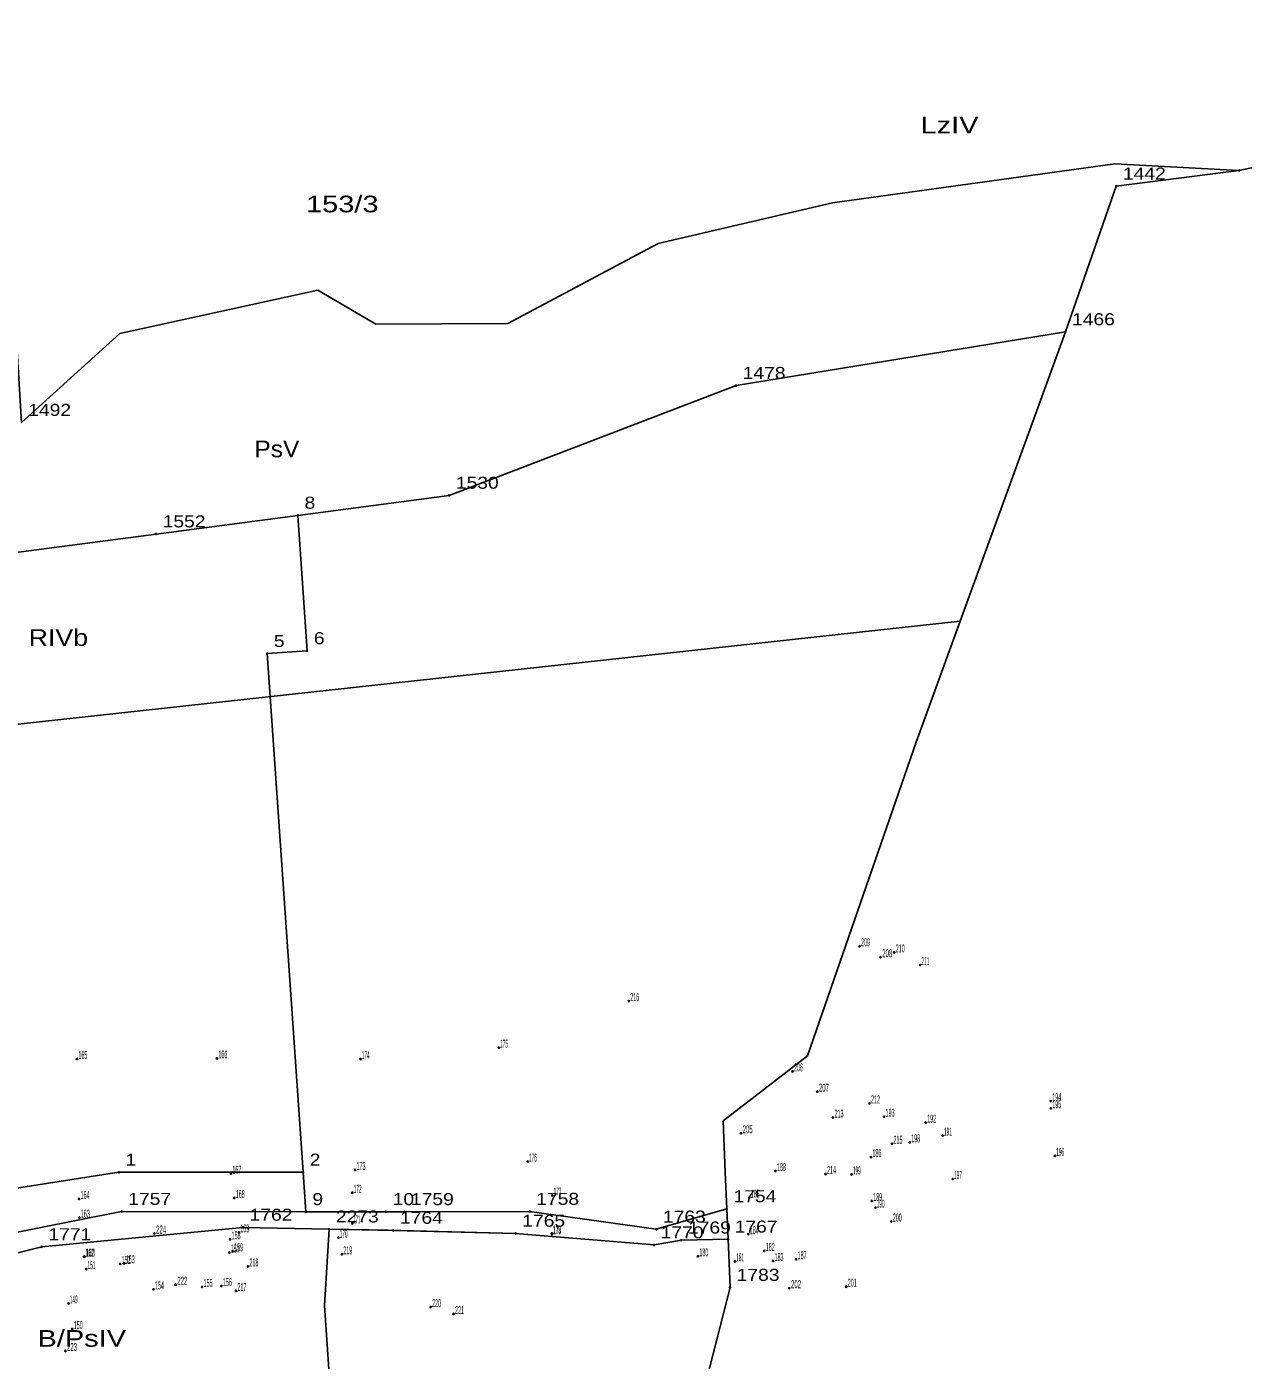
# Model space of a CAD drawing. Extents: x 4640203 to 4641683, y 5358965 to 5360242.
# Drawn here: x 4641163.8 to 4641255, y 5359988.8 to 5360088.9 of the extents above; entities that cross this region are included whole.
import ezdxf

# ---------------------------------------------------------------- set-up
doc = ezdxf.new("R2010")
doc.units = 0
doc.header["$LTSCALE"] = 0.36
doc.layers.add('24', color=7, linetype='Continuous')
doc.layers.add('26', color=7, linetype='Continuous')
for name, color, linetype, lineweight in [('25', 7, 'Continuous', 25), ('27', 7, 'Continuous', 25), ('63', 7, 'Continuous', 25), ('8', 7, 'Continuous', 25)]:
    doc.layers.add(name, color=color, linetype=linetype, lineweight=lineweight)

msp = doc.modelspace()

# ---------------------------------------------------------------- linework, layer by layer
at = {"layer": '25'}
msp.add_line((4641184.73, 5359999.98), (4641184.53, 5360002.94), dxfattribs=at)
for points in [[(4641151.72, 5360047.94), (4641173.5, 5360050.81), (4641184.14, 5360052.21), (4641195.49, 5360053.71), (4641217, 5360061.94), (4641241.7, 5360065.97), (4641245.52, 5360076.9), (4641254.72, 5360078.07), (4641265.56, 5360080.37)], [(4641139.68, 5359998.09), (4641170.72, 5360002.94), (4641184.53, 5360002.94), (4641181.84, 5360041.84), (4641184.84, 5360042.05), (4641184.14, 5360052.21)], [(4641158.71, 5359995.79), (4641164.93, 5359997.35), (4641180.02, 5359998.81), (4641186.49, 5359998.68), (4641191.3, 5359998.58), (4641200.47, 5359998.36), (4641210.85, 5359997.49), (4641212.9, 5359997.85), (4641216.4, 5359997.92), (4641216.31, 5360000.2), (4641211.02, 5359998.67), (4641201.52, 5360000), (4641192.12, 5359999.98), (4641190.75, 5359999.98), (4641184.73, 5359999.98), (4641170.92, 5360000), (4641145.57, 5359994.97)], [(4641124.54, 5359992.92), (4641124.61, 5359989.61), (4641124.88, 5359976.54), (4641158.96, 5359977.43), (4641186.91, 5359979.03), (4641212.95, 5359980.26), (4641216.55, 5359994.3), (4641216.4, 5359997.92)]]:
    msp.add_lwpolyline(points, dxfattribs=at)
at = {"layer": '27'}
for points in [[(4641256.47, 5360097.81), (4641247.03, 5360099.15), (4641232.91, 5360100.84), (4641215.68, 5360091.36), (4641196.97, 5360092.27), (4641179.55, 5360092.08), (4641161.24, 5360094.8), (4641163.42, 5360059.17), (4641170.79, 5360065.86), (4641185.64, 5360069.11), (4641189.99, 5360066.54), (4641199.88, 5360066.6), (4641211.17, 5360072.59), (4641224.24, 5360075.65), (4641233.66, 5360076.96), (4641245.4, 5360078.58), (4641254.72, 5360078.07), (4641265.56, 5360080.37)], [(4641241.7, 5360065.97), (4641245.52, 5360076.9), (4641254.72, 5360078.07)], [(4641233.82, 5360044.27), (4641241.7, 5360065.97), (4641217, 5360061.94), (4641195.49, 5360053.71), (4641184.14, 5360052.21), (4641173.5, 5360050.81), (4641151.72, 5360047.94), (4641132.16, 5360045.29), (4641115.06, 5360042.61), (4641102.5, 5360040.4), (4641098.15, 5360039.71), (4641089.62, 5360038.35), (4641066.2, 5360034.85), (4641054.92, 5360034.23), (4641049.01, 5360031.54), (4641040.7, 5360028.74), (4641036.69, 5360026.02)], [(4641216.31, 5360000.2), (4641216.18, 5360002.94), (4641216.03, 5360006.8), (4641222.35, 5360011.68), (4641230.52, 5360035.19), (4641233.82, 5360044.27), (4641141.19, 5360034.16), (4641052.15, 5360025.2), (4641039.9, 5359991.64)], [(4641186.49, 5359998.68), (4641190.9, 5359998.59), (4641200.47, 5359998.36), (4641210.85, 5359997.49), (4641212.9, 5359997.85), (4641216.4, 5359997.92), (4641216.31, 5360000.2), (4641211.02, 5359998.67), (4641201.52, 5360000), (4641192.12, 5359999.98), (4641190.75, 5359999.98), (4641184.73, 5359999.98), (4641170.92, 5360000), (4641145.57, 5359994.97), (4641140.14, 5359994.9), (4641120.73, 5359995.15), (4641111.55, 5359994.83), (4641066.92, 5359989.11), (4641045.09, 5359990.59), (4641039.9, 5359991.64), (4641023.69, 5359994.9)]]:
    msp.add_lwpolyline(points, dxfattribs=at)
msp.add_lwpolyline([(4641158.71, 5359995.79), (4641158.96, 5359977.43), (4641186.91, 5359979.03), (4641186.81, 5359983.04), (4641186.13, 5359992.94), (4641186.49, 5359998.68), (4641180.02, 5359998.81), (4641164.93, 5359997.35)], close=True, dxfattribs=at)
at = {"layer": '63'}
for centre in [(4641226.27, 5360019.89), (4641226.27, 5360019.89), (4641228.87, 5360019.43), (4641228.87, 5360019.43), (4641227.84, 5360019.07), (4641227.84, 5360019.07), (4641230.81, 5360018.48), (4641230.81, 5360018.48), (4641208.96, 5360015.78), (4641208.96, 5360015.78), (4641167.57, 5360011.44), (4641167.57, 5360011.44), (4641178.07, 5360011.48), (4641178.07, 5360011.48), (4641188.84, 5360011.43), (4641188.84, 5360011.43), (4641199.21, 5360012.29), (4641199.21, 5360012.29), (4641221.24, 5360010.51), (4641221.24, 5360010.51), (4641223.09, 5360008.99), (4641223.09, 5360008.99), (4641227.01, 5360008.11), (4641227.01, 5360008.11), (4641240.61, 5360008.28), (4641240.61, 5360008.28), (4641240.61, 5360007.74), (4641240.61, 5360007.74), (4641224.28, 5360007.05), (4641224.28, 5360007.05), (4641228.11, 5360007.11), (4641228.11, 5360007.11), (4641231.23, 5360006.67), (4641231.23, 5360006.67), (4641217.37, 5360005.87), (4641217.37, 5360005.87), (4641232.5, 5360005.69), (4641232.5, 5360005.69), (4641228.7, 5360005.08), (4641228.7, 5360005.08), (4641230.03, 5360005.19), (4641230.03, 5360005.19), (4641201.38, 5360003.75), (4641201.38, 5360003.75), (4641227.12, 5360004.08), (4641227.12, 5360004.08), (4641240.92, 5360004.17), (4641240.92, 5360004.17), (4641179.12, 5360002.84), (4641179.12, 5360002.84), (4641188.43, 5360003.12), (4641188.43, 5360003.12), (4641219.96, 5360003.03), (4641219.96, 5360003.03), (4641223.72, 5360002.81), (4641223.72, 5360002.81), (4641225.67, 5360002.78), (4641225.67, 5360002.78), (4641233.26, 5360002.44), (4641233.26, 5360002.44), (4641188.23, 5360001.41), (4641188.23, 5360001.41), (4641167.73, 5360000.94), (4641167.73, 5360000.94), (4641179.37, 5360001.02), (4641179.37, 5360001.02), (4641203.22, 5360001.2), (4641203.22, 5360001.2), (4641217.99, 5360001.04), (4641217.99, 5360001.04), (4641227.18, 5360000.79), (4641227.18, 5360000.79), (4641167.75, 5359999.54), (4641167.75, 5359999.54), (4641227.46, 5360000.29), (4641227.46, 5360000.29), (4641179.71, 5359998.44), (4641179.71, 5359998.44), (4641188.23, 5359999.11), (4641188.23, 5359999.11), (4641228.65, 5359999.25), (4641228.65, 5359999.25), (4641173.38, 5359998.35), (4641173.38, 5359998.35), (4641179.06, 5359997.91), (4641179.06, 5359997.91), (4641187.18, 5359998.04), (4641187.18, 5359998.04), (4641203.18, 5359998.36), (4641203.18, 5359998.36), (4641203.2, 5359998.29), (4641203.2, 5359998.29), (4641217.93, 5359998.3), (4641217.93, 5359998.3), (4641168.09, 5359996.61), (4641168.09, 5359996.61), (4641168.14, 5359996.62), (4641168.14, 5359996.62), (4641179, 5359996.92), (4641179, 5359996.92), (4641179.25, 5359997.02), (4641179.25, 5359997.02), (4641187.44, 5359996.79), (4641187.44, 5359996.79), (4641214.14, 5359996.64), (4641214.14, 5359996.64), (4641219.12, 5359997.05), (4641219.12, 5359997.05), (4641221.51, 5359996.42), (4641221.51, 5359996.42), (4641168.27, 5359995.68), (4641168.27, 5359995.68), (4641170.81, 5359996.07), (4641170.81, 5359996.07), (4641171.12, 5359996.11), (4641171.12, 5359996.11), (4641180.4, 5359995.88), (4641180.4, 5359995.88), (4641216.92, 5359996.26), (4641216.92, 5359996.26), (4641219.78, 5359996.29), (4641219.78, 5359996.29), (4641174.97, 5359994.51), (4641174.97, 5359994.51), (4641178.41, 5359994.41), (4641178.41, 5359994.41), (4641173.31, 5359994.16), (4641173.31, 5359994.16), (4641176.96, 5359994.35), (4641176.96, 5359994.35), (4641179.5, 5359994.04), (4641179.5, 5359994.04), (4641221, 5359994.25), (4641221, 5359994.25), (4641225.27, 5359994.36), (4641225.27, 5359994.36), (4641166.94, 5359993.11), (4641166.94, 5359993.11), (4641194.1, 5359992.83), (4641194.1, 5359992.83), (4641195.82, 5359992.32), (4641195.82, 5359992.32), (4641167.22, 5359991.18), (4641167.22, 5359991.18), (4641166.7, 5359989.54), (4641166.7, 5359989.54)]:
    msp.add_circle(centre, 0.05, dxfattribs=at)
at = {"layer": '8'}
for centre in [(4641254.72, 5360078.07), (4641245.52, 5360076.9), (4641241.7, 5360065.97), (4641217, 5360061.94), (4641195.49, 5360053.71), (4641184.14, 5360052.21), (4641173.5, 5360050.81), (4641181.84, 5360041.84), (4641184.84, 5360042.05), (4641170.72, 5360002.94), (4641184.53, 5360002.94), (4641170.92, 5360000), (4641184.73, 5359999.98), (4641190.75, 5359999.98), (4641192.12, 5359999.98), (4641201.52, 5360000), (4641216.31, 5360000.2), (4641180.02, 5359998.81), (4641186.49, 5359998.68), (4641191.3, 5359998.58), (4641211.02, 5359998.67), (4641200.47, 5359998.36), (4641210.85, 5359997.49), (4641212.9, 5359997.85), (4641216.4, 5359997.92), (4641164.93, 5359997.35), (4641216.55, 5359994.3)]:
    msp.add_circle(centre, 0.045, dxfattribs=at)

# ---------------------------------------------------------------- texts
at = {"layer": '24', "width": 1.3}
msp.add_text('153/3', height=1.25, dxfattribs=at).set_placement((4641184.75, 5360074.94))
at = {"layer": '26'}
for s, width, p in [('LzIV', 1.3, (4641230.84, 5360080.86)), ('PsV', 1.1, (4641180.88, 5360056.57)), ('RIVb', 1.2, (4641163.95, 5360042.42)), ('B/PsIV', 1.3, (4641164.61, 5359989.86))]:
    msp.add_text(s, height=1.25, dxfattribs=dict(at, width=width)).set_placement(p)
at = {"layer": '63'}
for s, width, p in [(' 209', 0.4, (4641226.27, 5360019.89)), (' 209', 0.4, (4641226.27, 5360019.89)), (' 208', 0.45, (4641227.84, 5360019.07)), (' 208', 0.45, (4641227.84, 5360019.07)), (' 210', 0.4, (4641228.87, 5360019.43)), (' 210', 0.4, (4641228.87, 5360019.43)), (' 211', 0.35, (4641230.81, 5360018.48)), (' 211', 0.35, (4641230.81, 5360018.48)), (' 216', 0.4, (4641208.96, 5360015.78)), (' 216', 0.4, (4641208.96, 5360015.78)), (' 175', 0.35, (4641199.21, 5360012.29)), (' 175', 0.35, (4641199.21, 5360012.29)), (' 165', 0.4, (4641167.57, 5360011.44)), (' 165', 0.4, (4641167.57, 5360011.44)), (' 166', 0.4, (4641178.07, 5360011.48)), (' 166', 0.4, (4641178.07, 5360011.48)), (' 174', 0.35, (4641188.84, 5360011.43)), (' 174', 0.35, (4641188.84, 5360011.43)), (' 206', 0.4, (4641221.24, 5360010.51)), (' 206', 0.4, (4641221.24, 5360010.51)), (' 207', 0.45, (4641223.09, 5360008.99)), (' 207', 0.45, (4641223.09, 5360008.99)), (' 212', 0.4, (4641227.01, 5360008.11)), (' 212', 0.4, (4641227.01, 5360008.11)), (' 194', 0.4, (4641240.61, 5360008.28)), (' 194', 0.4, (4641240.61, 5360008.28)), (' 213', 0.4, (4641224.28, 5360007.05)), (' 213', 0.4, (4641224.28, 5360007.05)), (' 193', 0.4, (4641228.11, 5360007.11)), (' 193', 0.4, (4641228.11, 5360007.11)), (' 195', 0.4, (4641240.61, 5360007.74)), (' 195', 0.4, (4641240.61, 5360007.74)), (' 205', 0.45, (4641217.37, 5360005.87)), (' 205', 0.45, (4641217.37, 5360005.87)), (' 192', 0.4, (4641231.23, 5360006.67)), (' 192', 0.4, (4641231.23, 5360006.67)), (' 215', 0.4, (4641228.7, 5360005.08)), (' 215', 0.4, (4641228.7, 5360005.08)), (' 198', 0.4, (4641230.03, 5360005.19)), (' 198', 0.4, (4641230.03, 5360005.19)), (' 191', 0.35, (4641232.5, 5360005.69)), (' 191', 0.35, (4641232.5, 5360005.69)), (' 186', 0.4, (4641227.12, 5360004.08)), (' 186', 0.4, (4641227.12, 5360004.08)), (' 196', 0.35, (4641240.92, 5360004.17)), (' 196', 0.35, (4641240.92, 5360004.17)), (' 167', 0.4, (4641179.12, 5360002.84)), (' 167', 0.4, (4641179.12, 5360002.84)), (' 173', 0.4, (4641188.43, 5360003.12)), (' 173', 0.4, (4641188.43, 5360003.12)), (' 176', 0.35, (4641201.38, 5360003.75)), (' 176', 0.35, (4641201.38, 5360003.75)), (' 188', 0.4, (4641219.96, 5360003.03)), (' 188', 0.4, (4641219.96, 5360003.03)), (' 214', 0.4, (4641223.72, 5360002.81)), (' 214', 0.4, (4641223.72, 5360002.81)), (' 199', 0.35, (4641225.67, 5360002.78)), (' 199', 0.35, (4641225.67, 5360002.78)), (' 197', 0.35, (4641233.26, 5360002.44)), (' 197', 0.35, (4641233.26, 5360002.44)), (' 164', 0.4, (4641167.73, 5360000.94)), (' 164', 0.4, (4641167.73, 5360000.94)), (' 168', 0.4, (4641179.37, 5360001.02)), (' 168', 0.4, (4641179.37, 5360001.02)), (' 172', 0.35, (4641188.23, 5360001.41)), (' 172', 0.35, (4641188.23, 5360001.41)), (' 177', 0.35, (4641203.22, 5360001.2)), (' 177', 0.35, (4641203.22, 5360001.2)), (' 185', 0.4, (4641217.99, 5360001.04)), (' 185', 0.4, (4641217.99, 5360001.04)), (' 189', 0.4, (4641227.18, 5360000.79)), (' 189', 0.4, (4641227.18, 5360000.79)), (' 190', 0.35, (4641227.46, 5360000.29)), (' 190', 0.35, (4641227.46, 5360000.29)), (' 163', 0.4, (4641167.75, 5359999.54)), (' 163', 0.4, (4641167.75, 5359999.54)), (' 171', 0.3, (4641188.23, 5359999.11)), (' 171', 0.3, (4641188.23, 5359999.11)), (' 200', 0.4, (4641228.65, 5359999.25)), (' 200', 0.4, (4641228.65, 5359999.25)), (' 224', 0.45, (4641173.38, 5359998.35)), (' 224', 0.45, (4641173.38, 5359998.35)), (' 158', 0.4, (4641179.06, 5359997.91)), (' 158', 0.4, (4641179.06, 5359997.91)), (' 169', 0.4, (4641179.71, 5359998.44)), (' 169', 0.4, (4641179.71, 5359998.44)), (' 170', 0.35, (4641187.18, 5359998.04)), (' 170', 0.35, (4641187.18, 5359998.04)), (' 179', 0.35, (4641203.18, 5359998.36)), (' 179', 0.35, (4641203.18, 5359998.36)), (' 178', 0.35, (4641203.2, 5359998.29)), (' 178', 0.35, (4641203.2, 5359998.29)), (' 184', 0.4, (4641217.93, 5359998.3)), (' 184', 0.4, (4641217.93, 5359998.3)), (' 157', 0.4, (4641179, 5359996.92)), (' 157', 0.4, (4641179, 5359996.92)), (' 159', 0.4, (4641179.25, 5359997.02)), (' 159', 0.4, (4641179.25, 5359997.02)), (' 182', 0.4, (4641219.12, 5359997.05)), (' 182', 0.4, (4641219.12, 5359997.05)), (' 162', 0.4, (4641168.09, 5359996.61)), (' 162', 0.4, (4641168.09, 5359996.61)), (' 160', 0.4, (4641168.14, 5359996.62)), (' 160', 0.4, (4641168.14, 5359996.62)), (' 152', 0.4, (4641170.81, 5359996.07)), (' 152', 0.4, (4641170.81, 5359996.07)), (' 153', 0.4, (4641171.12, 5359996.11)), (' 153', 0.4, (4641171.12, 5359996.11)), (' 218', 0.4, (4641180.4, 5359995.88)), (' 218', 0.4, (4641180.4, 5359995.88)), (' 219', 0.4, (4641187.44, 5359996.79)), (' 219', 0.4, (4641187.44, 5359996.79)), (' 180', 0.4, (4641214.14, 5359996.64)), (' 180', 0.4, (4641214.14, 5359996.64)), (' 181', 0.35, (4641216.92, 5359996.26)), (' 181', 0.35, (4641216.92, 5359996.26)), (' 183', 0.4, (4641219.78, 5359996.29)), (' 183', 0.4, (4641219.78, 5359996.29)), (' 187', 0.4, (4641221.51, 5359996.42)), (' 187', 0.4, (4641221.51, 5359996.42)), (' 151', 0.35, (4641168.27, 5359995.68)), (' 151', 0.35, (4641168.27, 5359995.68)), (' 154', 0.4, (4641173.31, 5359994.16)), (' 154', 0.4, (4641173.31, 5359994.16)), (' 222', 0.45, (4641174.97, 5359994.51)), (' 222', 0.45, (4641174.97, 5359994.51)), (' 155', 0.4, (4641176.96, 5359994.35)), (' 155', 0.4, (4641176.96, 5359994.35)), (' 156', 0.4, (4641178.41, 5359994.41)), (' 156', 0.4, (4641178.41, 5359994.41)), (' 217', 0.4, (4641179.5, 5359994.04)), (' 217', 0.4, (4641179.5, 5359994.04)), (' 202', 0.45, (4641221, 5359994.25)), (' 202', 0.45, (4641221, 5359994.25)), (' 201', 0.4, (4641225.27, 5359994.36)), (' 201', 0.4, (4641225.27, 5359994.36)), (' 149', 0.35, (4641166.94, 5359993.11)), (' 149', 0.35, (4641166.94, 5359993.11)), (' 220', 0.4, (4641194.1, 5359992.83)), (' 220', 0.4, (4641194.1, 5359992.83)), (' 221', 0.4, (4641195.82, 5359992.32)), (' 221', 0.4, (4641195.82, 5359992.32)), (' 150', 0.4, (4641167.22, 5359991.18)), (' 150', 0.4, (4641167.22, 5359991.18)), (' 223', 0.45, (4641166.7, 5359989.54)), (' 223', 0.45, (4641166.7, 5359989.54))]:
    msp.add_text(s, height=0.6, dxfattribs=dict(at, width=width)).set_placement(p)
at = {"layer": '8', "width": 1.2}
for s, p in [('1442', (4641246.02, 5360077.4)), ('1466', (4641242.2, 5360066.47)), ('1478', (4641217.5, 5360062.44)), ('1492', (4641163.92, 5360059.67)), ('1530', (4641195.99, 5360054.21)), ('8', (4641184.64, 5360052.71)), ('1552', (4641174, 5360051.31)), ('6', (4641185.34, 5360042.55)), ('5', (4641182.34, 5360042.34)), ('1', (4641171.22, 5360003.44)), ('2', (4641185.03, 5360003.44)), ('1754', (4641216.81, 5360000.7)), ('1757', (4641171.42, 5360000.5)), ('9', (4641185.23, 5360000.48)), ('10', (4641191.25, 5360000.48)), ('1759', (4641192.62, 5360000.48)), ('1758', (4641202.02, 5360000.5)), ('1762', (4641180.52, 5359999.31)), ('2273', (4641186.99, 5359999.18)), ('1764', (4641191.8, 5359999.08)), ('1765', (4641200.97, 5359998.86)), ('1763', (4641211.52, 5359999.17)), ('1771', (4641165.43, 5359997.85)), ('1770', (4641211.35, 5359997.99)), ('1769', (4641213.4, 5359998.35)), ('1767', (4641216.9, 5359998.42)), ('1783', (4641217.05, 5359994.8))]:
    msp.add_text(s, height=0.9, dxfattribs=at).set_placement(p)

doc.saveas('drawing.dxf')
